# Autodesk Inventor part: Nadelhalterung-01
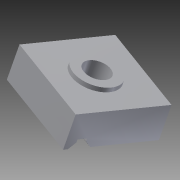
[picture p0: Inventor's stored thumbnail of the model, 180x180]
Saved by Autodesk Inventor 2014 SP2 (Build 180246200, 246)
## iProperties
Company: VDW-Nachwuchsstiftung
Created: 2014-04
Part Number: Nadelhalterung-01
Material: Aluminium 6061
Document SubType Name: Modeling
Designer: e_dammj
Density: 2.71 g/cm^3
Appearance: Aluminium - flach
Project: Verstellbarer Werkstückanschlag
Mass: 24.5784 g
Surface Area: 36.3222 cm^2
Volume: 9.06953 cm^3
Author: e_dammj
Title: Nadelhalterung
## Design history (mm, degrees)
sketch "Skizze1"
  geometry: L1 (-15, 15)-(15, 15); L2 (15, 15)-(15, -15); L3 (15, -15)-(-15, -15); L4 (-15, -15)-(-15, 15); L5 (-15, 15)-(15, -15); L6 (15, 15)-(-15, -15); 1 further point
  constraints: 12 end point, 2 midpoint, 2 parallel, 1 horizontal, 1 perpendicular
  dimensions: "d0" = 30 distance of L2.end L3.end; "d1" = 30 distance of L1.end L2.end
extrude "Grundkörper" new body sketch "Skizze1" distance "d2" = 11.5; taper "d3" = 0 deg
sketch "Skizze2"
  geometry: C1 r 7.5 at (0, 0); 1 further point
  constraints: 1 centre point, 1 coincident
  dimensions: "d4" = 15 diameter of C1
extrude "Ansatz D=15" join sketch "Skizze2" distance "d5" = 1.5; taper "d6" = 0 deg
sketch "Skizze3"
  geometry: 2 further points
  constraints: 1 coincident
hole "Senkbohrung" sketch "Skizze3" at (0, 0) diameter "d7" = 8.5; stored, may be unused: countersink angle "d11" = 90 deg, drill point angle "d13" = 118 deg; dims "d8" = 6, "d9" = 15, "d10" = 3.5, "d12" = 8
sketch "Skizze4"
  geometry: L1 (30, 0)-(0, 0) reference; L2 (0, 0)-(0, 11.5) reference; L3 (28.5, 0)-(26.5, 2); L4 (26.5, 2)-(26.5, 3); L5 (25, 4.983)-(25, -1.414); L6 (26.5, 3)-(25, 3); L7 (15, -2.352)-(15, 14.525); L8 (21.5, 0)-(23.5, 2); L9 (23.5, 2)-(23.5, 3); L10 (23.5, 3)-(25, 3); L11 (25, 0)-(28.5, 0); L12 (25, 0)-(21.5, 0); L13 (30, 0)-(30, 11.5) reference; L14 (-0.651, 5.75)-(31.282, 5.75); L15 (21.5, 11.5)-(23.5, 9.5); L16 (23.5, 9.5)-(23.5, 8.5); L17 (25, 11.5)-(21.5, 11.5); L18 (23.5, 8.5)-(25, 8.5); L19 (26.5, 9.5)-(26.5, 8.5); L20 (26.5, 8.5)-(25, 8.5); L21 (28.5, 11.5)-(26.5, 9.5); L22 (25, 11.5)-(28.5, 11.5); L23 (22.5, 13)-(7.5, 13) reference; L24 (22.5, 13)-(7.5, 13) reference; L25 (7.5, 11.5)-(22.5, 11.5) reference; L26 (7.5, 11.5)-(7.5, 13) reference; L27 (22.5, 11.5)-(22.5, 13) reference; L28 (22.5, 11.5)-(19.099, 11.5); L29 (19.099, 11.5)-(19.099, 13); L30 (19.099, 13)-(22.5, 13); L31 (22.5, 13)-(22.5, 11.5); 4 further points
  constraints: 46 end point, 12 symmetric about line, 7 point on line, 4 perpendicular, 3 parallel, 2 collinear, 2 midpoint, 1 horizontal
  dimensions: "d15" = 3 diameter of L4 L5; "d16" = 10 distance between parallel lines of L7 L5; "d17" = 1 distance from line of L3.end L6; "d18" = 3 distance from line of L6 L3.start; "d19" = 45 deg angle of L5 L3; "d24" = 11.599 distance between parallel lines of L26 L29
  node "Projizierte Kontur1"
extrude "Nut Unterteil" cut sketch "Skizze4" stored distance "d20" = 1.5; taper "d21" = 0 deg
extrude "Nut Oberteil" cut sketch "Skizze4" stored distance "d22" = 1.5; taper "d23" = 0 deg
node "Volumenkörper1"
